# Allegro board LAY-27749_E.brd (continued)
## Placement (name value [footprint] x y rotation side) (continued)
C3899  0.1uF  [CC0402_HD]  92.43 35.28 0 top
C3900  10uF  [CC0603_OV]  92.43 36.75 0 top
C5116  1uF  [CC0402_HD]  34.8 87 0 top
C5117  1uF  [CC0402_HD]  34.9 82.93 0 top
C5118  1uF  [CC0402_HD]  29.76 81.92 180 top
C5119  1uF  [CC0402_HD]  29.82 87.25 180 top
C5120  1uF  [CC0402_HD]  36.07 79.38 180 top
C5121  1uF  [CC0402_HD]  36.01 73.92 180 top
C5122  180uF  [CCE10_3X10_3]  15.88 228.09 270 top
C5123  560uF  [CC7343A_LP]  21.57 216.53 90 bottom
C5124  560uF  [CC7343A_LP]  34.58 216.81 90 bottom
C5125  22uF  [CC0805_OV]  33.78 228.16 270 top
C5126  22uF  [CC0805_OV]  22.86 227.33 270 top
C5127  100uF  [CC1210]  21.38 216.06 90 top
C5128  100uF  [CC1210]  34.44 216.29 90 top
C5129  100uF  [CC1210]  38.03 216.25 90 top
C5130  100uF  [CC1210]  17.7 216.06 90 top
C5131  0.1uF  [CC0402_HD]  27.22 231.55 0 bottom
C5132  100pF  [CC0402_HD]  29.31 234.6 270 bottom
C5133  0.022UF  [CC0402_HD]  26 234.62 90 bottom
C5134  10uF  [CC0603_OV]  34.84 231.55 0 top
C5135  0.1uF  [CC0402_HD]  31.8 232.57 0 bottom
C5136  22pF  [CC0402_HD]  27.02 234.62 90 top
C5137  330pF  [CC0402_HD]  28.16 234.62 270 top
C5138  22uF  [1206_CC]  30.58 109.14 180 top
C5139  1uF  [CC0603_OV]  30.55 115.83 0 top
C5140  10uF  [CC1206_OV]  175.39 195.45 90 top
C5141  0.1uF  [CC0402_HD]  181.36 190.94 0 bottom
C5142  10uF  [CC1206_OV]  30.36 190.24 180 top
C5143  0.1uF  [CC0402_HD]  34.87 196.21 90 bottom
C5144  10uF  [CC1206_OV]  174.75 190.19 270 top
C5145  10uF  [CC1206_OV]  172.47 190.19 270 top
C5146  10uF  [CC0603_OV]  168.21 190.5 0 top
C5147  10uF  [CC1206_OV]  35.62 187.32 0 top
C5148  10uF  [CC1206_OV]  35.62 189.61 0 top
C5149  0.1uF  [CC0402_HD]  31.93 161.54 0 top
C5150  1uF  [CC0603_OV]  31.95 167.03 270 top
C5151  10uF  [CC1206_OV]  23.7 163.22 90 top
C5152  10uF  [CC1206_OV]  25.86 163.22 90 top
C5153  0.1uF  [CC0402_HD]  27.51 163.22 270 top
C5154  22uF  [1206_CC]  29.16 172.49 180 top
C5155  22uF  [1206_CC]  29.16 170.21 180 top
C5156  22uF  [1206_CC]  29.16 174.9 180 top
C5157  1uF  [CC0603_OV]  29.12 176.89 0 top
C5158  0.047UF  [CC0603_OV]  30.56 167.03 90 top
C5159  0.1uF  [CC0402_HD]  33.53 136.93 0 top
C5160  1uF  [CC0603_OV]  33.55 142.42 270 top
C5161  10uF  [CC1206_OV]  25.3 138.61 90 top
C5162  10uF  [CC1206_OV]  27.46 138.61 90 top
C5163  0.1uF  [CC0402_HD]  29.11 138.61 270 top
C5164  22uF  [1206_CC]  30.76 147.88 180 top
C5165  22uF  [1206_CC]  30.76 145.59 180 top
C5166  22uF  [1206_CC]  30.76 150.29 180 top
C5167  1uF  [CC0603_OV]  30.72 152.28 0 top
C5168  0.047UF  [CC0603_OV]  32.16 142.42 90 top
C5171  0.1uF  [CC0402_HD]  96.16 85.42 180 bottom
C5174  10pF  [CC0402_HD]  141.47 47.15 90 top
C5175  10pF  [CC0402_HD]  141.47 50.15 270 top
C5176  0.1uF  [CC0402_HD]  136.21 56.9 180 bottom
C5178  0.1uF  [CC0402_HD]  161.4 52.07 0 bottom
C5179  0.1uF  [CC0402_HD]  161.4 48.91 0 bottom
C5180  0.1uF  [CC0402_HD]  179.32 41.9 90 bottom
C5181  0.1uF  [CC0402_HD]  172.3 44.39 90 bottom
C5182  0.1uF  [CC0402_HD]  166.79 44.39 90 bottom
C5183  0.1uF  [CC0402_HD]  160.93 44.39 90 bottom
C5184  10uF  [CC0603_OV]  140.72 41.66 90 top
C5185  0.1uF  [CC0402_HD]  172.59 54.94 270 bottom
C5186  0.1uF  [CC0402_HD]  178.44 43.94 90 bottom
C5187  0.1uF  [CC0402_HD]  173.81 54.94 270 bottom
C5188  0.1uF  [CC0402_HD]  166.79 54.94 270 bottom
C5189  0.1uF  [CC0402_HD]  173.79 44.39 90 bottom
C5190  0.1uF  [CC0402_HD]  170.79 44.39 90 bottom
C5191  0.1uF  [CC0402_HD]  164.3 54.94 270 bottom
C5192  0.1uF  [CC0402_HD]  168.3 44.39 90 bottom
C5193  0.1uF  [CC0402_HD]  162.79 44.39 90 bottom
C5194  0.1uF  [CC0402_HD]  165.3 44.39 90 bottom
C5195  0.1uF  [CC0402_HD]  176.3 44.39 90 bottom
C5196  0.1uF  [CC0402_HD]  176.3 54.94 270 bottom
C5197  10uF  [CC0603_OV]  113.3 41.01 270 top
C5198  0.1uF  [CC0402_HD]  177.88 51.61 180 bottom
C5199  0.1uF  [CC0402_HD]  162.3 54.94 270 bottom
C5200  0.1uF  [CC0402_HD]  169.79 54.94 270 bottom
C5201  0.1uF  [CC0402_HD]  179.83 47.38 270 bottom
C5202  0.1uF  [CC0402_HD]  206.2 65.51 90 top
C5203  1uF  [CC0603_OV]  200.71 65.53 0 top
C5204  10uF  [CC1206_OV]  204.52 57.28 180 top
C5205  10uF  [CC1206_OV]  204.52 59.44 180 top
C5206  0.1uF  [CC0402_HD]  204.52 61.09 0 top
C5207  22uF  [1206_CC]  197.54 62.74 270 top
C5208  22uF  [1206_CC]  195.25 62.74 270 top
C5209  22uF  [1206_CC]  192.84 62.74 270 top
C5210  1uF  [CC0603_OV]  190.85 62.7 90 top
C5211  0.047UF  [CC0603_OV]  200.71 64.14 180 top
C5213  0.1uF  [CC0402_HD]  137.67 47.38 270 bottom
C5214  0.1uF  [CC0402_HD]  119.24 48.91 0 bottom
C5215  0.1uF  [CC0402_HD]  120.13 54.94 270 bottom
C5216  0.1uF  [CC0402_HD]  135.71 51.61 180 bottom
C5217  0.1uF  [CC0402_HD]  127.63 54.94 270 bottom
C5218  0.1uF  [CC0402_HD]  119.24 52.07 0 bottom
C5219  0.1uF  [CC0402_HD]  119.24 51.16 0 bottom
C5220  0.1uF  [CC0402_HD]  119.24 53.16 0 bottom
C5221  0.1uF  [CC0402_HD]  118.45 56.04 0 bottom
C5222  0.1uF  [CC0402_HD]  135.66 50.15 180 bottom
C5223  0.1uF  [CC0402_HD]  135.66 52.7 180 bottom
C5224  0.1uF  [CC0402_HD]  129.29 54.94 270 bottom
C5225  0.1uF  [CC0402_HD]  136.06 54.65 270 bottom
C5226  0.1uF  [CC0402_HD]  126.13 54.94 270 bottom
C5227  0.1uF  [CC0402_HD]  124.63 44.39 90 bottom
C5228  0.1uF  [CC0402_HD]  118.77 44.39 90 bottom
C5229  0.1uF  [CC0402_HD]  130.13 44.39 90 bottom
C5230  0.1uF  [CC0402_HD]  137.16 41.9 90 bottom
C5231  0.1uF  [CC0402_HD]  136.27 43.94 90 bottom
C5232  0.1uF  [CC0402_HD]  124.63 54.94 270 bottom
C5233  0.1uF  [CC0402_HD]  134.13 54.94 270 bottom
C5234  0.1uF  [CC0402_HD]  131.64 54.94 270 bottom
C5235  0.1uF  [CC0402_HD]  134.13 44.39 90 bottom
C5236  0.1uF  [CC0402_HD]  128.63 44.39 90 bottom
C5237  0.1uF  [CC0402_HD]  123.13 44.39 90 bottom
C5238  0.1uF  [CC0402_HD]  130.43 54.94 270 bottom
C5239  0.1uF  [CC0402_HD]  120.63 44.39 90 bottom
C5240  0.1uF  [CC0402_HD]  122.13 54.94 270 bottom
C5241  0.1uF  [CC0402_HD]  131.63 44.39 90 bottom
C5242  0.1uF  [CC0402_HD]  126.13 44.39 90 bottom
C5243  0.1uF  [CC0402_HD]  250.6 90.27 90 top
C5244  1uF  [CC0603_OV]  245.11 90.3 0 top
C5245  22uF  [1206_CC]  239.65 87.5 270 top
C5246  22uF  [1206_CC]  241.94 87.5 270 top
C5247  22uF  [1206_CC]  237.24 87.5 270 top
C5248  1uF  [CC0603_OV]  235.25 87.47 90 top
C5249  0.047UF  [CC0603_OV]  245.11 88.9 180 top
C5250  10uF  [CC1206_OV]  248.92 82.04 180 top
C5251  10uF  [CC1206_OV]  248.92 84.2 180 top
C5252  0.1uF  [CC0402_HD]  248.92 85.85 0 top
C5253  0.1uF  [CC0402_HD]  178.37 56.9 180 bottom
C5254  10pF  [CC0402_HD]  183.63 47.15 90 top
C5255  10pF  [CC0402_HD]  183.63 50.15 270 top
C5256  10uF  [CC0603_OV]  155.32 58.17 90 top
C5257  10uF  [CC0603_OV]  182.88 41.66 90 top
C5258  10uF  [CC0603_OV]  155.46 41.01 270 top
C5259  0.1uF  [CC0402_HD]  41.34 211.41 180 top
C5260  1uF  [CC0402_HD]  83.39 227.61 90 bottom
C5261  100uF  [CC1210]  77.64 208.33 0 top
C5262  100uF  [CC1210]  106.19 207.37 90 bottom
C5263  100uF  [CC1210]  89.3 208.27 180 bottom
C5264  100uF  [CC1210]  89.3 208.33 180 top
C5265  560uF  [CC7343A_LP]  100.29 207.36 90 top
C5266  22uF  [CC0805]  98.16 226.21 270 bottom
C5267  560uF  [CC7343A_LP]  89.58 212.69 180 bottom
C5268  560uF  [CC7343A_LP]  89.58 212.69 180 top
C5269  0.01UF  [CC0402_HD]  67.2 224.61 0 bottom
C5270  10pF  [CC0402_HD]  87.07 217.96 0 bottom
C5271  330pF  [CC0402_HD]  87.57 216.43 90 bottom
C5272  470pF  [CC0402_25]  88.72 217.44 270 bottom
C5273  1uF  [CC0402_HD]  94.79 227.39 180 bottom
C5274  1uF  [CC0402_HD]  94.79 227.39 180 top
C5275  0.22uF  [CC0402_HD]  87.85 224.54 90 bottom
C5276  0.1uF  [CC0402_HD]  94.68 234.78 180 top
C5277  22UF  [CC1210]  94.66 237.04 180 top
C5278  22UF  [CC1210]  94.66 237.1 180 bottom
C5279  330uF  [CAP_10P5_RAD]  92.5 246.99 180 top
C5280  100uF  [CC1210]  77.51 204.46 0 top
C5281  560uF  [CC7343A_LP]  77.59 212.69 0 top
C5282  560uF  [CC7343A_LP]  77.59 212.69 0 bottom
C5283  330uF  [CAP_10P5_RAD]  111.69 246.99 0 top
C5284  22uF  [CC0805]  71.55 228.86 90 bottom
C5285  1uF  [CC0402_HD]  76.6 227.79 180 top
C5286  0.1uF  [CC0402_HD]  76.59 235.15 180 top
C5287  22UF  [CC1210]  76.58 237.41 180 top
C5288  22UF  [CC1210]  76.58 237.46 180 bottom
C5289  330uF  [CAP_10P5_RAD]  78.96 246.99 180 top
C5290  100uF  [CC1210]  89.3 204.5 180 top
C5291  2.2uF  [CC0402_HD]  108.56 207.36 90 top
C5292  0.1uF  [CC0402_HD]  109.52 207.36 90 bottom
C5293  0.1uF  [CC0402_HD]  109.52 207.36 90 top
C5294  0.1uF  [CC0402_HD]  119.38 34.92 90 top
C5295  0.1uF  [CC0402_HD]  121.36 34.92 90 top
C5296  0.1uF  [CC0402_HD]  141.15 34.92 90 top
C5297  0.1uF  [CC0402_HD]  143.13 34.92 90 top
C5298  0.1uF  [CC0402_HD]  162.92 34.92 90 top
C5299  0.1uF  [CC0402_HD]  164.9 34.92 90 top
C5300  0.1uF  [CC0402_HD]  186.67 34.92 90 top
C5301  0.1uF  [CC0402_HD]  184.69 34.92 90 top
C5302  0.1uF  [CC0402_HD]  184.12 87.5 90 bottom
C5303  0.1uF  [CC0402_HD]  200.95 102.08 90 bottom
C5304  0.1uF  [CC0402_HD]  202.31 103.76 180 bottom
C5305  0.1uF  [CC0402_HD]  200.95 108.66 270 bottom
C5306  0.1uF  [CC0402_HD]  202.31 104.85 180 bottom
C5307  0.1uF  [CC0402_HD]  202.31 106.98 180 bottom
C5308  1uF  [CC0402_HD]  204.05 94.15 270 bottom
C5309  0.1uF  [CC0402_HD]  254.2 111.43 0 top
C5310  0.1uF  [CC0402_HD]  130.12 86.54 0 top
C5311  0.1uF  [CC0402_HD]  130.12 85.5 0 top
C5312  0.022UF  [CC0402_HD]  202.83 97.41 90 top
C5313  0.022UF  [CC0402_HD]  195.47 97.41 90 top
C5314  0.022UF  [CC0402_HD]  195.41 114.42 270 top
C5315  0.022UF  [CC0402_HD]  203.11 114.3 270 top
C5316  0.022UF  [CC0402_HD]  186 82.83 90 top
C5317  0.022UF  [CC0402_HD]  178.64 82.83 90 top
C5318  0.022UF  [CC0402_HD]  178.59 99.84 270 top
C5319  0.022UF  [CC0402_HD]  186.28 99.72 270 top
C5320  1uF  [CC0402_HD]  86.78 42.88 0 top
C5321  1uF  [CC0402_HD]  86.78 41.88 0 top
C5324  0.1uF  [CC0402_HD]  236.47 131.71 90 top
C5327  0.1uF  [CC0402_HD]  104.44 98.22 180 top
C5328  0.1uF  [CC0402_HD]  105.69 92.68 180 top
C5329  0.1uF  [CC0402_HD]  112.32 98.22 0 top
C5330  0.1uF  [CC0402_HD]  113.57 92.68 0 top
C5333  0.1uF  [CC0402_HD]  241.81 188.85 180 top
C5334  0.1uF  [CC0402_HD]  277.34 77.71 180 top
C5337  330uF  [CAP_10P5_RAD]  207.9 238.67 90 top
C5338  330uF  [CAP_10P5_RAD]  187.32 224.19 90 top
C5339  330uF  [CAP_10P5_RAD]  191.64 238.67 90 top
C5340  330uF  [CAP_10P5_RAD]  15.81 145.24 0 top
C5341  330uF  [CAP_10P5_RAD]  35.18 29.34 0 top
C5342  330uF  [CAP_10P5_RAD]  26.92 29.34 180 top
C5343  1uF  [CC0402_HD]  98.56 230.55 90 top
C5344  1uF  [CC0402_HD]  80.81 230.88 0 top
C5345  1F  [CAP_5X19P2_TH]  266.89 76.01 0 top
CN3  CONN_SD_CARD 9  [CON_SDCARD_28P9X29_SM_RA]  92.7 17.54 0 top
CN4  USB_TYPE_A_DUAL  [CON_USB_8F_TH_RA]  36.5 13.22 0 top
CT24  470uF  [CC7343A]  127.39 190.12 0 top
CT28  470uF  [CAP_10P5_RAD]  15.39 131.57 0 top
CT29  470uF  [CC7343A]  119.25 127.75 270 top
CT30  470uF  [CC7343A]  90.17 124.33 180 top
CT31  470uF  [CAP_10P5_RAD]  17.27 119.76 0 top
CT32  470uF  [CC7343A]  108.46 120.52 0 top
CT35  470uF  [CAP_10P5_RAD]  16.92 92.96 0 top
CT40  470uF  [CC7343A]  87.5 191.4 90 bottom
CT41  470uF  [CC7343A]  137.43 179.32 0 bottom
CT42  470uF  [CC7343A]  68.33 178.31 270 bottom
CT43  470uF  [CC7343A]  60.33 178.3 270 bottom
CT44  470uF  [CC7343A]  68.2 165.6 270 bottom
CT45  470uF  [CC7343A]  60.33 165.6 270 bottom
CT46  470uF  [CC7343A]  60.33 154.05 270 bottom
CT47  470uF  [CC7343A]  137.43 151.38 0 bottom
CT48  470uF  [CC7343A]  137.43 146.43 0 bottom
CT54  470uF  [CC7343A]  171.45 153.67 0 top
CT55  470uF  [CC7343A]  172.21 204.72 0 top
D9  CMHD3595  [SOD123_A]  30.35 43.74 90 top
D10  CMHD3595  [SOD123_A]  40.39 43.74 90 top
D46  BAS116GW  [SOD-123]  273.41 81.09 270 top
ESD1  RClamp0531T  [DIODE_BIDIR_0402]  70.48 29.34 0 top
ESD2  RClamp0531T  [DIODE_BIDIR_0402]  68.33 29.34 0 top
ESD3  RClamp0531T  [DIODE_BIDIR_0402]  64.01 29.34 0 top
ESD4  RClamp0531T  [DIODE_BIDIR_0402]  66.17 29.34 0 top
ESD5  RClamp0531T  [DIODE_BIDIR_0402]  61.85 29.34 0 top
ESD6  RClamp0531T  [DIODE_BIDIR_0402]  59.69 29.34 0 top
ESD7  RClamp0531T  [DIODE_BIDIR_0402]  57.53 29.34 0 top
ESD8  RClamp0531T  [DIODE_BIDIR_0402]  55.37 29.34 0 top
ESD9  RClamp0531T  [DIODE_BIDIR_0402]  78.62 34.77 180 top
ESD10  RClamp0531T  [DIODE_BIDIR_0402]  95.68 35.23 0 top
F1  SMD300F/15  [FUSE_SMD050]  92.96 45.54 270 top
FAN1  HDR 1X4 WLOCK  [HDR4_2P54_TH]  196.04 51.85 270 top
FAN2  HDR 1X4 WLOCK  [HDR4_2P54_TH]  143.76 249.33 180 top
FAN3  HDR 1X4 WLOCK  [HDR4_2P54_TH]  41.73 249.33 180 top
FAN4  HDR 1X4 WLOCK  [HDR4_2P54_TH]  63.64 249.33 180 top
FAN5  HDR 1X4 WLOCK  [HDR4_2P54_TH]  9.84 249.33 180 top
FAN12  HDR 1X4 WLOCK  [HDR4_2P54_TH]  20.96 249.33 180 top
FB1  60OHM  [IND_1P8X1MM_SM]  239.32 236.55 90 top
FB9  120OHM  [IND_0603]  109.73 132.46 270 top
FB10  120OHM  [IND_0603]  111.12 132.46 270 top
FB11  120OHM  [IND_0603]  92.33 129.29 270 top
FB12  120OHM  [IND_0603]  93.85 129.29 270 top
FB16  120OHM  [IND_0603]  104.52 124.71 90 top
FB17  120OHM  [IND_0603]  106.55 124.71 90 top
FB18  120OHM  [IND_0603]  108.58 124.71 90 top
FB19  120OHM  [IND_0603]  110.11 124.71 90 top
FB20  120OHM  [IND_0603]  99.44 124.08 270 top
FB23  60OHM  [IND_1P8X1MM_SM]  114.55 110.53 270 top
FB24  120OHM  [IND_0603]  38.3 115.7 180 top
FB25  120OHM  [IND_0603]  36.04 118.9 270 top
FB26  120OHM  [IND_0603]  66.52 158.22 90 bottom
FB38  100 OHM  [IND_0805]  92.43 38.66 0 top
FB47  120OHM  [IND_0603]  96.14 192.15 270 bottom
FB48  120OHM  [IND_0603]  94.74 192.15 270 bottom
FB49  120OHM  [IND_0603]  92.46 192.15 270 bottom
FB50  120OHM  [IND_0603]  90.68 192.15 270 bottom
FB51  120OHM  [IND_0603]  72.26 171.58 0 bottom
FB52  120OHM  [IND_0603]  72.26 170.05 0 bottom
FB53  120OHM  [IND_0603]  72.26 168.4 0 bottom
FB54  120OHM  [IND_0603]  72.26 167 0 bottom
FB55  120OHM  [IND_0603]  72.57 148.51 270 bottom
FB56  120OHM  [IND_0603]  86.36 147.32 180 bottom
FB70  100 OHM  [IND_0805]  270.79 30.22 270 top
FB71  100 OHM  [IND_0805]  203.5 30.22 270 top
FB72  100 OHM  [IND_0805]  200.56 30.22 270 top
FB81  100 OHM  [IND_0805]  172.21 194.18 0 top
FB84  100 OHM  [IND_0805]  31.63 187.07 90 top
FB86  100 OHM  [IND_0805]  41.72 215.58 90 top
FB87  60OHM  [IND_1P8X1MM_SM]  102.26 110.53 270 top
FB89  60OHM  [IND_1P8X1MM_SM]  143.55 56.74 180 top
FB90  60OHM  [IND_1P8X1MM_SM]  142.37 41.61 270 top
FB91  60OHM  [IND_1P8X1MM_SM]  111.67 40.96 90 top
FB92  60OHM  [IND_1P8X1MM_SM]  143.1 44.75 180 top
FB93  60OHM  [IND_1P8X1MM_SM]  111.2 58.19 270 top
FB95  60OHM  [IND_1P8X1MM_SM]  153.37 58.19 270 top
FB96  60OHM  [IND_1P8X1MM_SM]  184.53 41.61 270 top
FB97  60OHM  [IND_1P8X1MM_SM]  153.84 40.96 90 top
FB98  60OHM  [IND_1P8X1MM_SM]  185.72 56.74 180 top
FB99  60OHM  [IND_1P8X1MM_SM]  185.24 44.75 180 top
FB101  120OHM  [IND_0603]  34.73 175.13 0 top
FL6  1.5uF  [CC_NFM41P_1806]  9.08 236.94 0 top
FL13  NFM18PC225B1A3  [CC0603_NFM18PC]  117.93 77.24 270 top
FL14  NFM18PC225B1A3  [CC0603_NFM18PC]  132.92 83.97 0 top
FL15  NFM18PC225B1A3  [CC0603_NFM18PC]  128.47 77.11 90 top
FL16  NFM18PC225B1A3  [CC0603_NFM18PC]  121.36 72.8 270 top
FL17  NFM18PC225B1A3  [CC0603_NFM18PC]  132.92 86.89 0 top
FL18  NFM18PC225B1A3  [CC0603_NFM18PC]  124.16 72.8 270 top
FL19  NFM18PC225B1A3  [CC0603_NFM18PC]  128.04 92.61 90 top
FL20  NFM18PC225B1A3  [CC0603_NFM18PC]  113.87 81.54 0 top
FL21  NFM18PC225B1A3  [CC0603_NFM18PC]  130.63 77.11 270 top
FL22  NFM18PC225B1A3  [CC0603_NFM18PC]  123.65 92.61 90 top
FL23  NFM18PC225B1A3  [CC0603_NFM18PC]  132.92 81.31 0 top
FL24  NFM18PC225B1A3  [CC0603_NFM18PC]  119.2 92.61 90 top
FL25  NFM18PC225B1A3  [CC0603_NFM18PC]  185.31 79.58 90 bottom
FL26  NFM18PC225B1A3  [CC0603_NFM18PC]  202.13 94.15 90 bottom
H1  MOUNTING HOLE  [MH315-158T_6P]  28 247 0 top
H2  MOUNTING HOLE  [MH315-158T_6P]  175.6 247 0 top
H3  MOUNTING HOLE  [MH315-158T_6P]  279 247 0 top
H4  MOUNTING HOLE  [MH315-158T_6P]  64 199.12 0 top
H5  MOUNTING HOLE  [MH315-158T_6P]  136 199.12 0 top
H6  MOUNTING HOLE  [MH315-158T_6P]  175.6 175 0 top
H7  MOUNTING HOLE  [MH315-158T_6P]  227 247 0 top
H8  MOUNTING HOLE  [MH315-158T_6P]  279 127.75 0 top
H9  MOUNTING HOLE  [MH315-158T_6P]  6 150.1 0 top
H10  MOUNTING HOLE  [MH315-158T_6P]  64 127.12 0 top
H11  MOUNTING HOLE  [MH315-158T_6P]  136 127.12 0 top
H12  MOUNTING HOLE  [MH315-158T_6P]  69.8 97 0 top
H13  MOUNTING HOLE  [MH315-158T_6P]  139.8 66 0 top
H14  MOUNTING HOLE  [MH315-158T_6P]  69.8 45 0 top
H15  MOUNTING HOLE  [MH315-158T_6P]  279 19 0 top
H16  MOUNTING HOLE  [MH315-158T_6P]  6 19 0 top
J2  CON_2X8  [HDR208_4W]  256.41 249.56 270 top
J3  CON PCI 98  [CON_PCIE_98_1MM_TH_122L]  202.65 231.65 270 top
J4  HDR 1X3  [HDR1X3_50MIL_335H]  239.9 205.99 90 top
J5  CON_240_DIMM  [CON_240_DDR3_DIMM_SKT]  46.75 237 270 top
J6  CON_240_DIMM  [CON_240_DDR3_DIMM_SKT]  153.25 114 90 top
J7  CON_240_DIMM  [CON_240_DDR3_DIMM_SKT]  160.85 237 270 top
J8  CON 2X4  [CONN_2X4_165_TH]  4.07 162 270 top
J9  CON_2X12_PWR  [CON_ATXPWR_2X12_A]  4.07 91.77 180 top
J10  HDR 1X7  [CON_7_SATA_V_SM]  22.78 49.02 270 top
J11  RJ45 13X2PORTS  [CON_RJ45_2X1_MAG_LED]  115.36 14.13 0 top
J12  RJ45 13X2PORTS  [CON_RJ45_2X1_MAG_LED]  137.13 14.13 0 top
J13  RJ45 13X2PORTS  [CON_RJ45_2X1_MAG_LED]  158.9 14.13 0 top
J14  RJ45 13X2PORTS  [CON_RJ45_2X1_MAG_LED]  180.67 14.13 0 top
J16  ZSFP+ 1x4 + SKT_20 SMT  [SUBASSY_SFP_34_CAGE_1X4_49P8X61P85]  208.35 11.71 90 top
J55  HDR 1X3  [HDR1X3_50MIL_335H]  239.78 212.22 90 top
J69  HDR_1X5  [HDR105]  37.26 64.03 90 top
J105  HDR_2X5  [HDR205_HTST_SM]  7.69 71.43 0 top
J106  CON_2X6 TH  [CON12_SHRD_2MM_TH]  128.57 238.59 90 top
JP7  HDR 1X3  [HDR1X3_50MIL_335H]  46.02 79.38 270 top
JP8  HDR 1X3  [HDR1X3_50MIL_335H]  72.29 81.28 90 top
L1  1uH  [IND2_SQ6P9_3_SM]  37.94 105.65 90 top
L3  1.5uH  [IND_IHLP]  102.5 246.99 0 top
L4  175nH  [IND2_10P4X8]  74.41 221.68 90 top
L5  175nH  [IND2_10P4X8]  92.5 221.31 90 top
L7  0.33uH  [IND2_744308033]  28.29 218.22 0 top
L23  90 OHM@100MHZ  [IND_0805_4P]  43.28 20.65 90 top
L24  90 OHM@100MHZ  [IND_0805_4P]  40.77 20.65 90 top
L26  100 OHM  [IND_0805]  30.35 38.73 270 top
L27  100 OHM  [IND_0805]  40.39 38.73 270 top
L29  100 OHM  [IND_0805]  204.04 46.99 0 top
L30  100 OHM  [IND_0805]  204.04 52.7 0 top
L31  100 OHM  [IND_0805]  269.67 52.7 180 top
L32  100 OHM  [IND_0805]  269.67 46.99 180 top
L52  10UH  [IND_2016A]  67.06 36.9 270 bottom
L53  10UH  [IND_2016A]  58.42 36.96 270 bottom
L54  1uH  [IND2_SQ6P9_3_SM]  36.52 166.71 90 top
L55  1uH  [IND2_SQ6P9_3_SM]  38.12 142.09 90 top
L56  1uH  [IND2_SQ6P9_3_SM]  201.03 70.1 180 top
L57  1uH  [IND2_SQ6P9_3_SM]  245.43 94.86 180 top
LAN1  CON_RJ45  [CON16_RJ45_JACK_50MIL_RA_TH]  65.45 24.32 0 top
LED1  LED_GRN  [LED_0603]  6.32 32.82 0 top
LED2  LED_GRN  [LED_0603]  6.32 34.34 0 top
LED3  LED_GRN  [LED_0603]  6.32 35.86 0 top
LED4  LED_GRN  [LED_0603]  6.32 37.39 0 top
LED5  GRN GRN DUAL  [LED_DUAL_553_TH]  273.56 7.19 0 top
LED6  GRN GRN DUAL  [LED_DUAL_553_TH]  202.69 7.19 0 top
NOREF  -  []  42.2 138.64 90 top
NOREF#2  -  []  140.72 53.9 0 top
NOREF#3  -  []  155.58 53.42 0 top
NOREF#4  -  []  200.81 163.69 0 top
NOREF#5  -  []  79.73 153.96 0 top
NOREF#6  -  []  68.68 146.55 0 top
NOREF#7  -  []  78.77 229.61 90 top
NOREF#8  -  []  29.87 164.57 0 top
NOREF#9  -  []  184.82 56.24 0 top
NOREF#10  -  []  272.75 97.89 90 top
NOREF#11  -  []  242.71 94.86 0 top
NOREF#12  -  []  32.25 140.13 0 top
NOREF#13  -  []  110.08 149.78 0 top
NOREF#14  -  []  78.52 10.59 90 top
NOREF#15  -  []  49.43 73.32 0 top
NOREF#16  -  []  160.57 59.16 0 top
NOREF#17  -  []  264.39 76.01 0 top
NOREF#18  -  []  114.31 52.76 0 top
NOREF#19  -  []  139.96 54.75 0 top
NOREF#20  -  []  -12.6 53.97 0 top
NOREF#21  -  []  30.63 44.11 0 top
NOREF#22  -  []  152.87 59.09 0 top
NOREF#23  -  []  76.07 151.9 0 top
NOREF#24  -  []  73.8 233.91 0 top
NOREF#25  -  []  239.99 -12.92 90 top
NOREF#26  -  []  55.29 8.86 90 top
NOREF#27  -  []  196.3 178.54 90 top
NOREF#28  -  []  155.58 54.87 0 top
NOREF#29  -  []  219.82 221.65 90 top
NOREF#30  -  []  142.37 40.77 90 top
NOREF#31  -  []  85.03 42.57 90 top
NOREF#32  -  []  247.39 83.89 90 top
NOREF#33  -  []  72.2 48.2 0 top
NOREF#34  -  []  182.89 53.9 0 top
NOREF#35  -  []  13.74 53.97 90 top
NOREF#36  -  []  153.34 40.06 90 top
NOREF#37  -  []  106.6 151.82 0 top
NOREF#38  -  []  32.55 41.64 0 top
NOREF#39  -  []  60.37 24.32 0 top
NOREF#40  -  []  111.17 40.06 90 top
NOREF#41  -  []  118.75 60.57 0 top
NOREF#42  -  []  69.51 4.29 90 top
NOREF#43  -  []  281.4 22.2 0 top
NOREF#44  -  []  37.94 102.92 90 top
NOREF#45  -  []  156.47 49.18 0 top
NOREF#46  -  []  276.09 79.32 0 top
NOREF#47  -  []  182.89 51.71 0 top
NOREF#48  -  []  202.65 221.65 90 top
NOREF#49  -  []  111.67 40.12 90 top
NOREF#50  -  []  229.4 250.2 0 top
NOREF#51  -  []  184.03 42.51 0 top
NOREF#52  -  []  66.4 130.32 0 top
NOREF#53  -  []  37.06 125.34 90 top
NOREF#54  -  []  219.82 198.65 90 top
NOREF#55  -  []  113.42 51.79 0 top
NOREF#56  -  []  215.92 167.23 0 top
NOREF#57  -  []  72.62 103.66 0 top
NOREF#58  -  []  251.1 11.71 0 top
NOREF#59  -  []  77.59 228.94 0 top
NOREF#60  -  []  127 88.73 90 top
NOREF#61  -  []  271.59 78.27 90 top
NOREF#62  -  []  142.65 56.24 0 top
NOREF#63  -  []  76.05 103.66 0 top
NOREF#64  -  []  142.26 44.75 0 top
NOREF#65  -  []  68.68 148.96 0 top
NOREF#66  -  []  153.34 40.06 0 top
NOREF#67  -  []  207.12 62.38 0 top
NOREF#68  -  []  153.87 57.29 90 top
NOREF#69  -  []  197.58 67.28 90 top
NOREF#70  -  []  235.61 11.3 90 top
NOREF#71  -  []  8.37 12.08 0 top
NOREF#72  -  []  28.87 164.57 0 top
NOREF#73  -  []  220.72 197.3 0 top
NOREF#74  -  []  93.12 137.12 0 top
NOREF#75  -  []  55.07 68.8 90 top
NOREF#76  -  []  118.97 73.93 0 top
NOREF#77  -  []  30.4 250.2 0 top
NOREF#78  -  []  208.35 11.71 90 top
NOREF#79  -  []  113.74 107.4 0 top
NOREF#80  -  []  60.86 35.55 90 top
NOREF#81  -  []  87.35 139.05 0 top
NOREF#82  -  []  31.47 139.96 0 top
NOREF#83  -  []  144.45 56.24 90 top
NOREF#84  -  []  55.07 80.8 0 top
NOREF#85  -  []  183.6 147.87 0 top
NOREF#86  -  []  185.64 140.84 0 top
NOREF#87  -  []  220.72 197.3 90 top
NOREF#88  -  []  245.34 88.99 0 top
NOREF#89  -  []  42.58 41.64 0 top
NOREF#90  -  []  30.77 138.11 90 top
NOREF#91  -  []  204.02 62.75 0 top
NOREF#92  -  []  156.47 55.93 0 top
NOREF#93  -  []  117.76 60.15 0 top
NOREF#94  -  []  269.8 143.27 0 top
NOREF#95  -  []  153.37 57.35 90 top
NOREF#96  -  [unnamed#2]  26.67 238.89 0 top
NOREF#97  -  []  139.96 50.82 0 top
NOREF#98  -  []  85.63 145.78 0 top
NOREF#99  -  []  -346.91 -208.36 0 top
NOREF#100  -  []  86.52 32.8 0 top
NOREF#101  -  []  263.65 170.18 0 top
NOREF#102  -  []  265.05 2.49 0 top
NOREF#103  -  []  66.72 8.86 90 top
NOREF#104  -  []  111.17 40.06 0 top
NOREF#105  -  []  269.88 11.13 90 top
NOREF#106  -  []  37.36 125.28 90 top
NOREF#107  -  []  96.05 174.8 0 top
NOREF#108  -  []  271.02 7.19 90 top
NOREF#109  -  []  113.42 54.87 0 top
NOREF#110  -  []  56.56 21.78 0 top
NOREF#111  -  []  271.02 7.19 90 top
NOREF#112  -  []  129.35 90.14 0 top
NOREF#113  -  []  81.13 42.86 0 top
NOREF#114  -  []  205.02 62.75 90 top
NOREF#115  -  []  276.84 79.82 0 top
NOREF#116  -  []  79.04 32.8 0 top
NOREF#117  -  []  113.42 47.21 0 top
NOREF#118  -  []  156.47 46.62 0 top
NOREF#119  -  []  201.4 179.85 90 top
NOREF#120  -  []  64.18 21.78 90 top
NOREF#121  -  []  23.39 232.94 0 top
NOREF#122  -  []  271.59 82.77 0 top
NOREF#123  -  []  202.65 231.65 0 top
NOREF#124  -  []  62.91 24.32 0 top
NOREF#125  -  []  55.07 80 90 top
NOREF#126  -  []  69.5 35.5 90 top
NOREF#127  -  []  82.61 42.97 0 top
NOREF#128  -  []  277.34 81.02 90 top
NOREF#129  -  []  239.99 -15.8 90 top
NOREF#130  -  []  272.75 97.89 0 top
NOREF#131  -  []  202.65 183.65 0 top
NOREF#132  -  []  200.15 7.19 90 top
NOREF#133  -  []  156.47 51.05 0 top
NOREF#134  -  []  198.78 -46.29 90 top
NOREF#135  -  []  86.51 142.61 0 top
NOREF#136  -  []  32.07 103.68 90 top
NOREF#137  -  []  68.68 145.4 0 top
NOREF#138  -  []  182.13 54.75 0 top
NOREF#139  -  []  99.02 32.8 0 top
NOREF#140  -  []  92.12 -8.29 90 top
NOREF#141  -  []  252.54 11.66 90 top
NOREF#142  -  []  22.25 10.86 0 top
NOREF#143  -  []  48.16 72.05 0 top
NOREF#144  -  []  40.6 163.26 90 top
NOREF#145  -  [unnamed#2]  279.4 8.89 0 top
NOREF#146  -  []  178 250.2 0 top
NOREF#147  -  []  238.82 234.65 90 top
NOREF#148  -  []  36.06 127.32 0 top
NOREF#149  -  []  128.19 90.18 0 top
NOREF#150  -  []  66.01 83.55 0 top
NOREF#151  -  []  38.12 139.37 90 top
NOREF#152  -  []  184.87 56.74 0 top
NOREF#153  -  []  103.6 151.82 0 top
NOREF#154  -  []  58.41 33.58 0 top
NOREF#155  -  []  8.4 153.3 0 top
NOREF#156  -  []  265.35 6.71 90 top
NOREF#157  -  []  102.08 173.85 0 top
NOREF#158  -  []  111.7 57.29 90 top
NOREF#159  -  []  208.35 11.71 90 top
NOREF#160  -  []  91.88 228.44 90 top
NOREF#161  -  []  203.17 62.45 90 top
NOREF#162  -  []  111.03 150.8 0 top
NOREF#163  -  []  184.34 44.25 0 top
NOREF#164  -  []  201.27 218.9 90 top
NOREF#165  -  []  208.35 11.71 0 top
NOREF#166  -  []  156.47 47.85 0 top
NOREF#167  -  []  8.37 12.08 0 top
NOREF#168  -  []  82 100.53 0 top
NOREF#169  -  [unnamed#2]  6.35 10.92 0 top
NOREF#170  -  []  66.72 8.86 90 top
NOREF#171  -  []  155.45 48.7 0 top
NOREF#172  -  []  208.35 11.71 90 top
NOREF#173  -  []  208.35 41.71 0 top
NOREF#174  -  []  80.02 8.49 0 top
NOREF#175  -  []  95.66 151.81 0 top
NOREF#176  -  []  182.44 121.21 0 top
NOREF#177  -  []  95.03 173.79 0 top
NOREF#178  -  []  184.4 44.75 0 top
NOREF#179  -  []  118.4 59.16 0 top
NOREF#180  -  []  40.66 44.11 0 top
NOREF#181  -  []  52.24 -2.03 0 top
NOREF#182  -  []  30.79 225.47 90 top
NOREF#183  -  []  283.38 2.5 90 top
NOREF#184  -  []  109.07 152.77 0 top
NOREF#185  -  []  211.68 41.71 0 top
NOREF#186  -  []  251.1 11.71 0 top
NOREF#187  -  []  222.6 6.71 90 top
NOREF#188  -  []  93.18 228.57 0 top
NOREF#189  -  []  241.98 92.05 90 top
NOREF#190  -  []  276.09 84.69 0 top
NOREF#191  -  []  186.3 162.95 0 top
NOREF#192  -  []  11.71 0.82 90 top
NOREF#193  -  []  9.76 -4.88 90 top
NOREF#194  -  []  269.8 176.04 0 top
NOREF#195  -  []  275.59 79.32 90 top
NOREF#196  -  []  142.71 56.74 0 top
NOREF#197  -  []  42.58 42.04 90 top
NOREF#198  -  []  30.2 140.13 90 top
NOREF#199  -  []  68.68 147.69 0 top
NOREF#200  -  []  89.02 32.8 0 top
NOREF#201  -  []  248.75 156.76 0 top
NOREF#202  -  []  194.18 2.49 0 top
NOREF#203  -  []  61.21 35.68 90 top
NOREF#204  -  []  26.29 226.07 0 top
NOREF#205  -  []  153.84 40.12 90 top
NOREF#206  -  []  201.4 179.85 90 top
NOREF#207  -  []  248.42 87.51 0 top
NOREF#208  -  []  251.1 11.71 0 top
NOREF#209  -  []  91.88 233.54 0 top
NOREF#210  -  []  113.31 48.81 0 top
NOREF#211  -  []  102.76 109.63 90 top
NOREF#212  -  []  33.7 170.16 0 top
NOREF#213  -  []  263.65 148.34 0 top
NOREF#214  -  []  138.4 202.32 0 top
NOREF#215  -  []  159.92 60.15 0 top
NOREF#216  -  []  36.52 163.98 90 top
NOREF#217  -  []  86.64 145.91 0 top
NOREF#218  -  []  49.43 72.05 0 top
NOREF#219  -  []  30.59 101.66 90 top
NOREF#220  -  []  58.28 33.23 0 top
NOREF#221  -  []  112.42 140.78 0 top
NOREF#222  -  []  111.86 141.67 0 top
NOREF#223  -  []  126.45 80.98 90 top
NOREF#224  -  []  53.16 18.01 0 top
NOREF#225  -  []  8.4 22.2 0 top
NOREF#226  -  []  271.27 168.91 90 top
NOREF#227  -  []  201.31 2.64 0 top
NOREF#228  -  []  72.62 149.03 0 top
NOREF#229  -  []  281.4 130.95 0 top
NOREF#230  -  []  81.08 134.92 0 top
NOREF#231  -  []  114.31 51.05 0 top
NOREF#232  -  []  82.4 137.66 0 top
NOREF#233  -  []  269.39 66.41 90 top
NOREF#234  -  []  78.33 103.66 0 top
NOREF#235  -  []  119.25 80.28 0 top
NOREF#236  -  []  78.52 10.59 0 top
NOREF#237  -  []  114.31 54.18 0 top
NOREF#238  -  []  25.04 234.21 0 top
NOREF#239  -  []  197.65 186.19 90 top
NOREF#240  -  []  142.2 69.2 0 top
NOREF#241  -  []  35.26 127.38 0 top
NOREF#242  -  []  91.03 174.8 0 top
NOREF#243  -  []  139.96 52.59 0 top
NOREF#244  -  []  77.19 103.66 0 top
NOREF#245  -  []  111.2 57.35 90 top
NOREF#246  -  []  269.8 154.19 0 top
NOREF#247  -  []  22.25 10.86 0 top
NOREF#248  -  []  28.23 102.2 90 top
NOREF#249  -  []  182.13 52.59 0 top
NOREF#250  -  []  247.57 88.21 90 top
NOREF#251  -  []  72.2 100.2 0 top
NOREF#252  -  []  11.51 236.23 90 top
NOREF#253  -  []  264.61 182.36 0 top
NOREF#254  -  []  6.7 236.94 90 top
NOREF#255  -  []  133.15 237.63 0 top
NOREF#256  -  []  155.58 49.96 0 top
NOREF#257  -  []  249.42 87.51 90 top
NOREF#258  -  []  6.26 -4.88 0 top
NOREF#259  -  []  251.52 87.15 0 top
NOREF#260  -  []  59.48 33.23 90 top
NOREF#261  -  []  52.5 24.32 0 top
NOREF#262  -  []  55.07 80.8 0 top
NOREF#263  -  []  79.92 101.65 0 top
NOREF#264  -  []  141.87 42.51 0 top
NOREF#265  -  []  239.32 235.7 90 top
NOREF#266  -  []  264.61 171.44 0 top
NOREF#267  -  []  269.8 165.11 0 top
NOREF#268  -  []  251.1 11.71 0 top
NOREF#269  -  []  202.65 181.65 0 top
NOREF#270  -  []  182.53 130.42 0 top
NOREF#271  -  []  271.02 7.19 0 top
NOREF#272  -  []  91.52 32.8 0 top
NOREF#273  -  []  66.72 8.86 90 top
NOREF#274  -  []  185.03 40.71 90 top
NOREF#275  -  []  201.4 220 0 top
NOREF#276  -  []  30.4 136 0 top
NOREF#277  -  []  186.14 44.25 90 top
NOREF#278  -  []  42.58 41.64 90 top
NOREF#279  -  []  114.31 49.18 0 top
NOREF#280  -  []  89.59 158.8 0 top
NOREF#281  -  []  184.53 40.77 90 top
NOREF#282  -  []  0 253 0 top
NOREF#283  -  []  197.5 242.42 0 top
NOREF#284  -  []  6.68 235.99 0 top
NOREF#285  -  []  112.05 149.85 0 top
NOREF#286  -  []  83.22 42.99 0 top
NOREF#287  -  []  93.56 150.85 0 top
NOREF#288  -  []  186.62 56.24 90 top
NOREF#289  -  []  101.76 111.43 0 top
NOREF#290  -  []  140.72 51.71 0 top
NOREF#291  -  []  201.4 179.85 90 top
NOREF#292  -  []  216.62 235.6 0 top
NOREF#293  -  []  33.99 75.71 0 top
NOREF#294  -  []  10.26 3.72 90 top
NOREF#295  -  []  281.4 250.2 0 top
NOREF#296  -  []  28.8 160.62 0 top
NOREF#297  -  []  113.42 53.42 0 top
NOREF#298  -  []  114.31 46.62 0 top
NOREF#299  -  []  74.65 150.94 0 top
NOREF#300  -  []  182.65 45.73 0 top
NOREF#301  -  []  219.82 230.65 90 top
NOREF#302  -  []  74.9 103.66 0 top
NOREF#303  -  []  263.65 181.1 0 top
NOREF#304  -  []  80.63 100.53 0 top
NOREF#305  -  []  115.05 110.43 90 top
NOREF#306  -  []  84.3 137.66 0 top
NOREF#307  -  []  142.2 44.25 0 top
NOREF#308  -  []  66.72 8.86 90 top
NOREF#309  -  []  0.98 0 90 top
NOREF#310  -  []  30.47 139.96 0 top
NOREF#311  -  []  182.13 50.82 0 top
NOREF#312  -  []  155.58 47.21 0 top
NOREF#313  -  []  75.61 231.89 0 top
NOREF#314  -  []  32.31 42.73 90 top
NOREF#315  -  []  96.85 229.24 90 top
NOREF#316  -  []  107.2 3.01 90 top
NOREF#317  -  []  109.63 172.81 0 top
NOREF#318  -  []  66.92 33.17 0 top
NOREF#319  -  []  241.98 98.95 0 top
NOREF#320  -  []  104.22 8.49 90 top
NOREF#321  -  []  109.6 95.45 0 top
NOREF#322  -  []  4.31 0.82 0 top
NOREF#323  -  []  76.55 155.05 0 top
NOREF#324  -  []  93.17 32.8 0 top
NOREF#325  -  []  81.29 101.65 0 top
NOREF#326  -  []  30.64 164.75 0 top
NOREF#327  -  []  17.75 17.3 0 top
NOREF#328  -  []  64.18 15.21 90 top
NOREF#329  -  []  75.92 148.96 0 top
NOREF#330  -  []  196.3 178.54 90 top
NOREF#331  -  []  93.39 83.5 0 top
NOREF#332  -  []  89.56 166.81 0 top
NOREF#333  -  []  73.8 228.81 90 top
NOREF#334  -  []  8.37 12.08 0 top
NOREF#335  -  [unnamed#2]  279.4 238.12 0 top
NOREF#336  -  []  200.15 7.19 0 top
NOREF#337  -  []  156.47 52.76 0 top
NOREF#338  -  []  197.5 242.42 0 top
NOREF#339  -  []  73.79 103.66 0 top
NOREF#340  -  []  217.97 194.7 90 top
NOREF#341  -  []  271.27 147.07 90 top
NOREF#342  -  []  82.47 43.32 0 top
NOREF#343  -  []  114.31 55.93 0 top
NOREF#344  -  []  81.13 137.66 0 top
NOREF#345  -  []  140.49 45.73 0 top
NOREF#346  -  []  42.34 42.73 90 top
NOREF#347  -  []  105.07 173.85 0 top
NOREF#348  -  []  74.52 143.88 0 top
NOREF#349  -  []  201.4 220 0 top
NOREF#350  -  []  29.17 162.72 90 top
NOREF#351  -  []  96.52 32.8 0 top
NOREF#352  -  []  247.57 87.21 90 top
NOREF#353  -  []  108.61 173.8 0 top
NOREF#354  -  []  22.25 17.3 0 top
NOREF#355  -  []  205.8 -4.93 0 top
NOREF#356  -  []  208.35 11.71 90 top
NOREF#357  -  []  102.26 109.69 90 top
NOREF#358  -  []  62.25 65.95 0 top
NOREF#359  -  []  82.4 139.05 0 top
NOREF#360  -  []  198.31 70.1 0 top
NOREF#361  -  []  199.01 11.13 90 top
NOREF#362  -  []  109.07 146.8 0 top
NOREF#363  -  []  25.79 225.47 0 top
NOREF#364  -  []  142.87 40.71 90 top
NOREF#365  -  []  267.9 -4.93 90 top
NOREF#366  -  []  155.58 51.73 0 top
NOREF#367  -  []  118 97.73 0 top
NOREF#368  -  []  26.97 103.68 0 top
NOREF#369  -  []  88.62 139.05 0 top
NOREF#370  -  []  79.26 100.53 0 top
NOREF#371  -  []  93.69 231.52 0 top
NOREF#372  -  []  271.27 157.99 90 top
NOREF#373  -  []  100.61 151.75 0 top
NOREF#374  -  []  203.17 63.45 90 top
NOREF#375  -  []  75.09 228.94 0 top
NOREF#376  -  []  60.86 35.55 0 top
NOREF#377  -  []  139.96 46.81 0 top
NOREF#378  -  []  48.16 74.59 0 top
NOREF#379  -  []  69.85 35.62 90 top
NOREF#380  -  []  66.4 202.32 0 top
NOREF#381  -  []  217.97 202.2 90 top
NOREF#382  -  []  203 59.12 90 top
NOREF#383  -  []  92.12 -3.19 90 top
NOREF#384  -  []  28.23 109.1 0 top
NOREF#385  -  []  75.92 143.88 0 top
NOREF#386  -  []  198.5 0.77 0 top
NOREF#387  -  []  30.29 226.07 90 top
NOREF#388  -  []  138.4 130.32 0 top
NOREF#389  -  []  117.55 80.98 0 top
NOREF#390  -  []  264.61 160.51 0 top
NOREF#391  -  []  29.17 162.72 90 top
NOREF#392  -  []  198.78 -46.29 0 top
NOREF#393  -  []  92.12 -2.09 90 top
NOREF#394  -  []  82.39 32.8 0 top
NOREF#395  -  []  31.29 103.51 0 top
NOREF#396  -  []  69.77 -2.03 90 top
NOREF#397  -  []  160.91 60.57 0 top
NOREF#398  -  []  113.42 49.96 0 top
NOREF#399  -  []  35.3 145.54 0 top
NOREF#400  -  []  54.07 81.8 0 top
NOREF#401  -  []  67.04 33.52 0 top
NOREF#402  -  []  28.59 164.75 90 top
NOREF#403  -  []  30.59 101.66 90 top
NOREF#404  -  []  55.29 8.86 0 top
NOREF#405  -  []  93.28 -57.65 0 top
NOREF#406  -  []  263.65 159.26 0 top
NOREF#407  -  []  208.35 41.71 90 top
NOREF#408  -  []  114.55 109.69 90 top
NOREF#409  -  []  30.23 99.56 0 top
NOREF#410  -  []  271.27 179.83 90 top
NOREF#411  -  []  264.39 66.41 0 top
NOREF#412  -  []  17.46 7.56 0 top
NOREF#413  -  []  9.85 24.53 0 top
NOREF#414  -  []  114.31 47.85 0 top
NOREF#415  -  []  106.1 148.65 0 top
NOREF#416  -  []  156.47 54.18 0 top
NOREF#417  -  []  30.77 138.11 90 top
NOREF#418  -  []  72.14 151.28 0 top
NOREF#419  -  []  9.08 236.13 90 top
NOREF#420  -  []  6.7 236.94 0 top
NOREF#421  -  []  182.13 46.81 0 top
NOREF#422  -  []  48.16 73.32 0 top
NOREF#423  -  []  68.12 33.17 90 top
NOREF#424  -  []  74.78 148.96 0 top
NOREF#425  -  []  178 178.2 0 top
NOREF#426  -  []  272.18 2.64 0 top
NOREF#427  -  []  93.06 173.79 0 top
NOREF#428  -  []  144 44.25 90 top
NOREF#429  -  []  84.09 32.8 0 top
NOREF#430  -  []  208.35 41.71 90 top
NOREF#431  -  []  30.29 103.51 0 top
NOREF#432  -  []  100.05 173.85 0 top
NOREF#433  -  []  94.58 152.83 0 top
NOREF#434  -  []  97.69 151.81 0 top
NOREF#435  -  []  97.06 173.79 0 top
NOREF#436  -  []  -306.71 305.3 0 top
NOREF#437  -  []  197.58 74.18 0 top
NOREF#438  -  []  75.54 153.91 0 top
NOREF#439  -  []  200.95 64.22 0 top
NOREF#440  -  []  251.1 11.71 0 top
NOREF#441  -  []  108.4 95.45 0 top
NOREF#442  -  []  32.55 41.64 0 top
NOREF#443  -  []  50.47 68.31 0 top
NOREF#444  -  []  69.5 35.5 0 top
NOREF#445  -  []  85.17 41.42 90 top
NOREF#446  -  []  106.52 11.79 90 top
NOREF#447  -  []  16.85 13.4 0 top
NOREF#448  -  []  238.82 235.65 0 top
NOREF#449  -  []  17.75 10.86 0 top
NOREF#450  -  []  275.4 84.69 0 top
NOREF#451  -  []  42.58 41.64 0 top
NOREF#452  -  []  84.42 41.74 90 top
NOREF#453  -  []  115.05 111.43 0 top
NOREF#454  -  []  110.7 59.09 0 top
NOREF#455  -  []  32.55 42.04 90 top
NOREF#456  -  []  197.4 0 90 top
NOREF#457  -  []  96.85 229.24 90 top
NOREF#458  -  []  200.15 7.19 90 top
NOREF#459  -  []  78.77 229.61 90 top
NOREF#460  -  []  54.07 67.8 90 top
NOREF#461  -  []  95.68 228.57 0 top
NOREF#462  -  []  81.13 139.05 0 top
NOREF#463  -  []  264.61 149.59 0 top
NOREF#464  -  []  219.82 218.65 90 top
NOREF#465  -  []  94.82 32.8 0 top
NOREF#466  -  []  115.49 89.17 0 top
NOREF#467  -  []  32.55 41.64 90 top
NOREF#468  -  [unnamed#2]  26.67 238.89 180 bottom
NOREF#469  -  [unnamed#2]  6.35 10.92 180 bottom
NOREF#470  -  [unnamed#2]  279.4 8.89 180 bottom
NOREF#471  -  [unnamed#2]  279.4 238.12 180 bottom
Q1  MMBT3906L  [SOT23]  102.28 225.41 0 top
Q2  MMBT3906L  [SOT23]  67.1 226.05 0 top
Q3  NX3008NBKW,115  [SC70_3]  203.2 18.92 180 top
Q4  NX3008NBKW,115  [SC70_3]  200.03 18.92 180 top
Q5  NX3008NBKW,115  [SC70_3]  273.18 23.57 180 top
Q6  NX3008NBKW,115  [SC70_3]  270.26 23.57 180 top
Q7  NX3008NBKW,115  [SC70_3]  10.39 30.91 90 top
Q8  NX3008NBKW,115  [SC70_3]  10.39 33.71 90 top
Q9  NX3008NBKW,115  [SC70_3]  10.39 36.5 90 top
Q10  NX3008NBKW,115  [SC70_3]  10.39 39.29 90 top
Q11  NX3008NBKW,115  [SC70_3]  17.4 22.86 180 top
Q12  NX3008NBKW,115  [SC70_3]  13.59 22.86 180 top
Q13  NX3008NBKW,115  [SC70_3]  15.88 107.06 180 top
R1  10.0  [RC0402_25]  33.85 101.87 90 top
R2  93.1K  [RC0402_25]  245.57 85.74 0 top
R3  29.4K  [RC0402_25]  246.13 87.12 90 top
R30  10.0  [RC0402_25]  243.71 233.68 180 top
R35  10.0  [RC0402_25]  243.71 232.66 180 top
R36  10.0  [RC0402_25]  254.63 232.66 0 top
R40  1.0K  [RC0402_HD]  80.81 228.76 180 top
R41  1.0K  [RC0402_HD]  80.81 229.79 180 top
R42  0  [RC0603_OV]  132.69 241.1 90 top
R43  1.0  [RC0805_OV]  84.14 216.43 270 bottom
R44  0  [RC0402_25]  80.86 232.7 0 top
R46  49.9  [RC0402_25]  77.64 202.17 0 bottom
R47  4.99K  [RC0402_25]  82.75 216.43 90 bottom
R48  4.99K  [RC0402_25]  82.37 227.61 270 bottom
R49  4.99K  [RC0402_25]  78.05 220.41 0 bottom
R50  24.9K  [RC0402_25]  76.91 229.13 180 bottom
R51  10.0  [RC0402_25]  254.63 231.65 0 top
R52  0  [RC0402_25]  68.65 221.22 180 top
R53  49.9  [RC0402_25]  122.02 213.21 90 top
R54  49.9  [RC0402_25]  122.02 218.62 90 bottom
R55  68.1K  [RC0402_25]  86.56 216.43 270 bottom
R56  2.05K  [RC0402_25]  122.02 214.38 90 bottom
R57  0  [RC0402_25]  84.91 227.61 270 bottom
R58  0  [RC0402_25]  86.94 227.61 270 bottom
R59  10.0K  [RC0402_25]  80.85 228.24 180 bottom
R60  24.9K  [RC0402_25]  78.05 221.64 0 bottom
R61  24.9K  [RC0402_25]  78.05 224.82 0 bottom
R62  24.9K  [RC0402_25]  76.28 225.83 180 bottom
R63  24.9K  [RC0402_25]  78.69 225.83 0 bottom
R64  24.9K  [RC0402_25]  80.85 227.23 180 bottom
R65  0  [RC0402_25]  88.6 222.78 90 bottom
R66  0  [RC0402_25]  86.94 222.91 270 top
R67  10.0K  [RC0402_25]  239.9 241.94 270 top
R68  10.0K  [RC0402_25]  242.44 241.94 270 top
R69  10.0K  [RC0402_25]  244.98 241.94 270 top
R70  10.0K  [RC0402_25]  247.52 241.94 270 top
R71  10.0K  [RC0402_25]  250.06 241.94 270 top
R72  10.0  [RC0402_25]  251.33 241.94 90 top
R73  10.0K  [RC0402_25]  253.87 241.94 270 top
R74  10.0K  [RC0402_25]  255.27 241.94 270 top
R75  2.67K  [RC0402_25]  98.27 221.99 0 top
R76  0  [RC0402_25]  98.27 220.85 0 top
R77  0  [RC0402_25]  98.94 232.33 0 top
R78  24.9K  [RC0402_25]  95 228.63 180 bottom
R92  1.0  [RC0805_OV]  24.56 229.27 90 bottom
R93  10.0  [RC0402_25]  30.45 234.6 270 bottom
R95  0  [RC0402_25]  23.67 234.6 90 top
R96  10.0K  [RC0402_25]  29.84 232.54 180 top
R97  255K  [RC0402_25]  26 234.62 90 top
R98  0  [RC0402_25]  30.45 234.6 270 top
R99  0  [RC0402_25]  28.16 234.62 90 bottom
R100  6.65K  [RC0402_25]  29.31 234.6 90 top
R101  0  [RC0402_25]  29.84 232.54 0 bottom
R102  10.0  [RC0402_25]  29.89 236.76 0 top
R103  0  [RC0402_25]  35.05 233.36 0 top
R104  49.9K  [RC0402_25]  27.02 234.62 90 bottom
R113  4.7K  [RC0402_25]  147.19 233.43 270 top
R119  4.7K  [RC0402_25]  194.56 227.71 180 top
R120  4.7K  [RC0402_25]  207.9 226.69 0 top
R124  4.7K  [RC0402_25]  227.33 227.97 0 top
R125  4.7K  [RC0402_25]  227.33 226.69 0 top
R128  4.7K  [RC0402_25]  207.9 224.54 0 top
R142  4.7K  [RC0402_25]  194.56 220.73 0 top
R143  4.7K  [RC0402_25]  227.33 224.79 0 top
R145  4.7K  [RC0402_25]  207.9 220.47 0 top
R146  4.7K  [RC0402_25]  215.26 220.09 0 top
R151  4.7K  [RC0402_25]  194.56 219.58 180 top
R175  0.33 OHM  [RC0402_25]  96.65 191.34 180 top
R176  0  [RC0402_25]  98.68 191.34 0 top
R177  0  [RC0402_25]  88.24 191.34 0 top
R178  0.33 OHM  [RC0402_25]  90.35 191.34 0 top
R179  0.33 OHM  [RC0402_25]  92.71 191.34 180 top
R180  0  [RC0402_25]  94.74 191.34 180 top
R181  0  [RC0402_25]  108.08 191.52 0 top
R182  0.33 OHM  [RC0402_25]  110.11 191.52 0 top
R190  10.0K  [RC0402_25]  250.95 205.64 270 top
R191  10.0K  [RC0402_25]  244.73 205.61 180 bottom
R192  10.0K  [RC0402_25]  242.7 205.61 270 top
R196  10.0K  [RC0402_25]  250.98 203.53 90 top
R197  10.0K  [RC0402_25]  111.05 188.59 270 top
R198  187  [RC0402_25]  117.35 188.72 90 top
R199  10.0K  [RC0402_25]  118.62 188.72 270 top
R200  10.0K  [RC0402_25]  119.63 188.72 270 top
R202  10.0K  [RC0402_25]  80.77 187.58 180 top
R203  10.0K  [RC0402_25]  242.7 203.58 90 top
R205  10.0K  [RC0402_25]  250.9 211.94 270 top
R206  4.7K  [RC0402_25]  215.26 221.36 180 top
R208  10.0K  [RC0402_25]  250.95 209.73 90 top
R211  10.0K  [RC0402_25]  125.21 181.61 180 top
R213  10.0K  [RC0402_25]  125.21 180.59 180 top
R217  4.7K  [RC0402_25]  242.57 209.8 90 top
R218  187  [RC0402_25]  125.22 178.31 0 top
R219  187  [RC0402_25]  73.03 178.18 180 top
R221  10.0K  [RC0402_25]  75.44 177.8 0 top
R222  4.7K  [RC0402_25]  242.57 211.84 270 top
R224  10.0K  [RC0402_25]  75.44 176.91 0 top
R229  10.0K  [RC0402_25]  75.44 174.62 0 top
R230  10.0K  [RC0402_25]  75.44 173.74 0 top
R232  187  [RC0402_25]  75.44 172.72 180 top
R233  0  [RC0402_25]  167.89 171.96 180 top
R234  0  [RC0402_25]  167.89 170.81 180 top
R250  4.7K  [RC0402_25]  75.44 159.51 0 top
R251  4.7K  [RC0402_25]  72.8 158.62 0 top
R252  4.7K  [RC0402_25]  72.77 157.54 0 top
R253  4.7K  [RC0402_25]  69.98 157.47 0 top
R254  4.7K  [RC0402_25]  69.98 156.21 0 top
R255  4.7K  [RC0402_25]  72.77 156.26 0 top
R257  4.7K  [RC0402_25]  69.98 154.94 0 top
R258  4.7K  [RC0402_25]  72.72 154.81 0 top
R259  187  [RC0402_25]  125.19 154.56 0 top
R260  4.7K  [RC0402_25]  69.98 154.05 0 top
R261  10.0K  [RC0402_25]  125.22 153.67 180 top
R262  4.7K  [RC0402_25]  69.98 153.16 0 top
R263  4.7K  [RC0402_25]  72.87 153.16 0 top
R264  10.0K  [RC0402_25]  125.22 152.78 180 top
R265  4.7K  [RC0402_25]  69.98 152.27 0 top
R266  4.7K  [RC0402_25]  69.98 151.38 0 top
R267  10.0K  [RC0402_25]  125.22 150.62 180 top
R268  4.7K  [RC0402_25]  69.98 150.24 180 top
R269  10.0K  [RC0402_25]  125.22 149.73 180 top
R270  330  [RC0402_25]  67.16 148.84 90 top
R271  187  [RC0402_25]  125.22 148.72 0 top
R273  0  [RC0603_OV]  65.84 149.22 270 top
R276  1K  [RC0402_25]  72.77 145.54 0 top
R277  1K  [RC0402_25]  75.44 145.54 0 top
R278  0  [RC0603_OV]  65.41 145.92 180 top
R279  4.7K  [RC0402_25]  75.44 142.62 0 top
R280  4.7K  [RC0402_25]  75.44 141.48 0 top
R285  0  [RC0603_OV]  65.41 142.11 180 top
R291  10.0K  [RC0402_25]  119.63 138.3 90 top
R294  4.7K  [RC0402_25]  78.49 137.03 90 top
R295  4.7K  [RC0402_25]  79.5 137.03 90 top
R296  33  [RC0402_25]  85.78 136.73 90 top
R297  4.7K  [RC0402_25]  86.79 136.73 90 top
R298  4.7K  [RC0402_25]  87.81 136.73 90 top
R299  4.7K  [RC0402_25]  88.7 136.73 270 top
R301  33  [RC0402_25]  91.31 137.03 270 top
R306  4.7K  [RC0402_25]  113.03 131.7 270 top
R307  4.7K  [RC0402_25]  114.05 131.7 90 top
R308  4.7K  [RC0402_25]  115.06 131.7 90 top
R309  4.7K  [RC0402_25]  116.08 131.7 270 top
R310  4.7K  [RC0402_25]  81.58 133.05 270 top
R311  0  [RC0402_25]  95.76 133.48 0 top
R312  0  [RC0402_25]  97.79 133.48 180 top
R313  0.33 OHM  [RC0402_25]  99.69 133.48 0 top
R314  0.33 OHM  [RC0402_25]  101.73 133.48 180 top
R315  0  [RC0402_25]  103.63 133.48 0 top
R316  0  [RC0402_25]  105.66 133.48 180 top
R317  0.33 OHM  [RC0402_25]  107.57 133.48 0 top
R318  0  [RC0402_25]  90.73 131.14 90 top
R319  0.33 OHM  [RC0402_25]  95.38 131.95 270 top
R320  4.7K  [RC0402_25]  113.03 128.91 270 top
R321  4.7K  [RC0402_25]  114.05 128.91 90 top
R322  4.7K  [RC0402_25]  115.06 128.91 90 top
R323  4.7K  [RC0402_25]  116.08 128.91 270 top
R332  1K  [RC0402_25]  3.4 32.82 0 top
R333  1K  [RC0402_25]  3.4 34.34 0 top
R335  1K  [RC0402_25]  3.4 35.86 0 top
R336  4.7K  [RC0402_25]  52.45 116.49 270 top
R337  4.7K  [RC0402_25]  15.37 113.16 180 top
R338  4.7K  [RC0402_25]  167.89 116 0 top
R341  1K  [RC0402_25]  3.4 37.39 0 top
R342  100  [RC0402_25]  15.37 112.14 0 top
R394  10.0K  [RC0402_25]  15.88 104.52 0 top
R508  17.4K  [RC0402_25]  43.18 40.39 180 top
R519  4.7K  [RC0402_25]  238.19 120.53 90 top
R520  4.7K  [RC0402_25]  237.1 120.53 90 top
R521  4.7K  [RC0402_25]  240.37 120.53 90 top
R522  4.7K  [RC0402_25]  239.28 120.53 90 top
R523  4.7K  [RC0402_25]  242.56 120.53 90 top
R524  4.7K  [RC0402_25]  100.48 88.32 270 bottom
R525  4.7K  [RC0402_25]  101.47 88.32 270 bottom
R526  4.7K  [RC0402_25]  243.64 120.53 90 top
R527  4.7K  [RC0402_25]  244.42 132.59 270 top
R528  4.7K  [RC0402_25]  245.51 132.59 270 top
R529  4.7K  [RC0402_25]  242.24 132.59 270 top
R530  4.7K  [RC0402_25]  243.33 132.59 270 top
R531  4.7K  [RC0402_25]  240.05 132.59 270 top
R532  100  [RC0402_25]  122.17 61.85 0 top
R533  100  [RC0402_25]  124.84 61.85 180 top
R534  100  [RC0402_25]  131.7 61.98 0 top
R535  100  [RC0402_25]  134.11 61.98 180 top
R536  100  [RC0402_25]  164.34 61.85 0 top
R537  100  [RC0402_25]  167 61.85 180 top
R538  100  [RC0402_25]  173.86 61.98 0 top
R539  100  [RC0402_25]  176.28 61.98 180 top
R614  0  [RC0402_25]  81.25 40.49 270 top
R627  0  [RC0402_25]  81.74 216.43 270 bottom
R628  4.99K  [RC0402_25]  80.72 216.43 90 bottom
R629  4.99K  [RC0402_25]  78.69 216.43 90 bottom
R630  0  [RC0402_25]  79.71 216.43 270 bottom
R631  0  [RC0402_25]  122.02 215.39 270 top
R632  0  [RC0402_25]  122.02 217.6 90 top
R637  100  [RC0402_25]  95.68 36.3 180 top
R641  330  [RC0402_25]  117.22 34.92 270 top
R642  330  [RC0402_25]  115.84 34.92 270 top
R643  330  [RC0402_25]  125.73 34.92 270 top
R644  330  [RC0402_25]  124.22 34.92 270 top
R645  330  [RC0402_25]  139.37 34.92 270 top
R646  330  [RC0402_25]  137.61 34.92 270 top
R647  330  [RC0402_25]  147.5 34.92 270 top
R648  330  [RC0402_25]  145.99 34.92 270 top
R649  330  [RC0402_25]  160.76 34.92 270 top
R650  330  [RC0402_25]  159.38 34.92 270 top
R651  330  [RC0402_25]  169.27 34.92 270 top
R652  330  [RC0402_25]  167.76 34.92 270 top
R654  330  [RC0402_25]  180.58 34.92 270 top
R655  330  [RC0402_25]  191.04 34.92 270 top
R656  330  [RC0402_25]  189.53 34.92 270 top
R659  18K  [RC0402_25]  29.34 43.94 270 bottom
R660  10.0K  [RC0402_25]  45.09 41.53 90 top
R661  10.0K  [RC0402_25]  35.05 41.53 90 top
R662  51.1K  [RC0402_25]  30.35 43.94 90 bottom
R663  18K  [RC0402_25]  39.37 43.94 270 bottom
R664  51.1K  [RC0402_25]  40.39 43.94 90 bottom
R665  180  [RC0402_25]  13.08 20.45 0 top
R666  180  [RC0402_25]  16.89 20.45 0 top
R667  100  [RC0402_25]  78.53 35.99 0 top
R669  100  [RC0402_25]  9.88 12.95 0 top
R670  100  [RC0402_25]  25.53 14.35 270 top
R671  4.7K  [RC0402_25]  9.88 11.94 180 top
R672  4.7K  [RC0402_25]  26.04 12.9 180 top
R685  5.1  [RC0402_25]  103.25 193.8 0 bottom
R686  5.1  [RC0402_25]  103.25 192.66 0 bottom
R687  5.1  [RC0402_25]  101.22 192.66 0 bottom
R689  5.1  [RC0402_25]  98.55 190.12 0 bottom
R690  5.1  [RC0402_25]  99.06 188.72 270 bottom
R691  5.1  [RC0402_25]  98.04 188.72 270 bottom
R693  698  [RC0402_25]  97.83 174.19 90 bottom
R694  200  [RC0402_25]  103.33 173.71 180 bottom
R695  698  [RC0402_25]  91.35 173.7 180 bottom
R696  10.0  [RC0402_25]  106.35 173.69 180 bottom
R697  200  [RC0402_25]  95.85 173.2 270 bottom
R698  0  [RC0402_25]  108.33 172.72 0 bottom
R699  10.0  [RC0402_25]  106.32 172.69 180 bottom
R700  49.9  [RC0402_25]  99.34 172.69 0 bottom
R701  49.9  [RC0402_25]  97.33 172.69 180 bottom
R703  0  [RC0402_25]  111.33 166.7 0 bottom
R705  0  [RC0402_25]  87.25 164.59 180 bottom
R706  10.0  [RC0402_25]  89.84 162.2 90 bottom
R707  10.0  [RC0402_25]  88.82 162.2 90 bottom
R708  5.1  [RC0402_25]  74.17 161.67 0 bottom
R709  10.0  [RC0402_25]  89.84 160.2 270 bottom
R710  10.0  [RC0402_25]  88.85 160.2 270 bottom
R711  0  [RC0402_25]  87.25 158.62 0 bottom
R712  0  [RC0603_OV]  75.13 154.46 270 bottom
R713  0  [RC0402_25]  113.33 157.69 0 bottom
R714  330  [RC0402_25]  93.33 156.69 0 bottom
R715  698  [RC0402_25]  90.32 156.69 180 bottom
R716  10.0  [RC0402_25]  111.33 155.69 0 bottom
R717  4.7K  [RC0402_25]  94.34 155.7 180 bottom
R718  698  [RC0402_25]  90.3 155.7 0 bottom
R720  4.7K  [RC0402_25]  110.34 154.71 0 bottom
R722  330  [RC0402_25]  78.87 154.31 270 bottom
R725  10.0  [RC0402_25]  111.84 154.2 270 bottom
R726  4.7K  [RC0402_25]  110.31 153.7 0 bottom
R727  200  [RC0402_25]  99.82 153.2 90 bottom
R730  49.9  [RC0402_25]  96.82 153.19 270 bottom
R731  49.9  [RC0402_25]  95.81 153.2 270 bottom
R732  4.7K  [RC0402_25]  79.38 152.53 180 bottom
R733  200  [RC0402_25]  106.32 152.69 180 bottom
R734  4.7K  [RC0402_25]  109.84 152.2 90 bottom
R735  4.7K  [RC0402_25]  107.82 152.2 90 bottom
R736  49.9  [RC0402_25]  90.32 151.69 0 bottom
R737  698  [RC0402_25]  92.84 151.21 270 bottom
R738  698  [RC0402_25]  99.95 150.11 270 bottom
R739  4.7K  [RC0402_25]  110.82 149.2 90 bottom
R740  4.7K  [RC0402_25]  109.35 148.72 0 bottom
R741  49.9  [RC0402_25]  90.35 148.69 0 bottom
R742  4.7K  [RC0402_25]  111.85 148.2 90 bottom
R743  10.0K  [RC0402_25]  88.82 148.21 270 bottom
R744  4.7K  [RC0402_25]  110.34 147.7 0 bottom
R745  10.0  [RC0402_25]  110.34 146.69 0 bottom
R746  4.7K  [RC0402_25]  112.34 146.7 0 bottom
R747  10.0K  [RC0402_25]  91.82 145.19 90 bottom
R748  100  [RC0402_25]  15.88 109.47 180 top
R750  4.7K  [RC0402_25]  80.77 144.15 90 bottom
R751  4.7K  [RC0402_25]  111.33 143.69 0 bottom
R753  4.7K  [RC0402_25]  111.33 142.7 0 bottom
R756  4.7K  [RC0402_25]  110.83 141.15 270 bottom
R757  4.7K  [RC0402_25]  109.32 141.68 0 bottom
R758  4.7K  [RC0402_25]  84.26 141.6 0 bottom
R759  4.7K  [RC0402_25]  82.23 141.73 0 bottom
R761  0  [RC0402_25]  87.86 141.22 270 bottom
R762  4.7K  [RC0402_25]  91.57 139.06 90 bottom
R763  4.7K  [RC0402_25]  90.68 139.06 90 bottom
R764  1K  [RC0402_25]  89.79 139.06 90 bottom
R765  1K  [RC0402_25]  88.9 139.06 90 bottom
R766  4.7K  [RC0402_25]  86.87 139.06 90 bottom
